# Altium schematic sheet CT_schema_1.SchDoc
size 725 x 521 mm
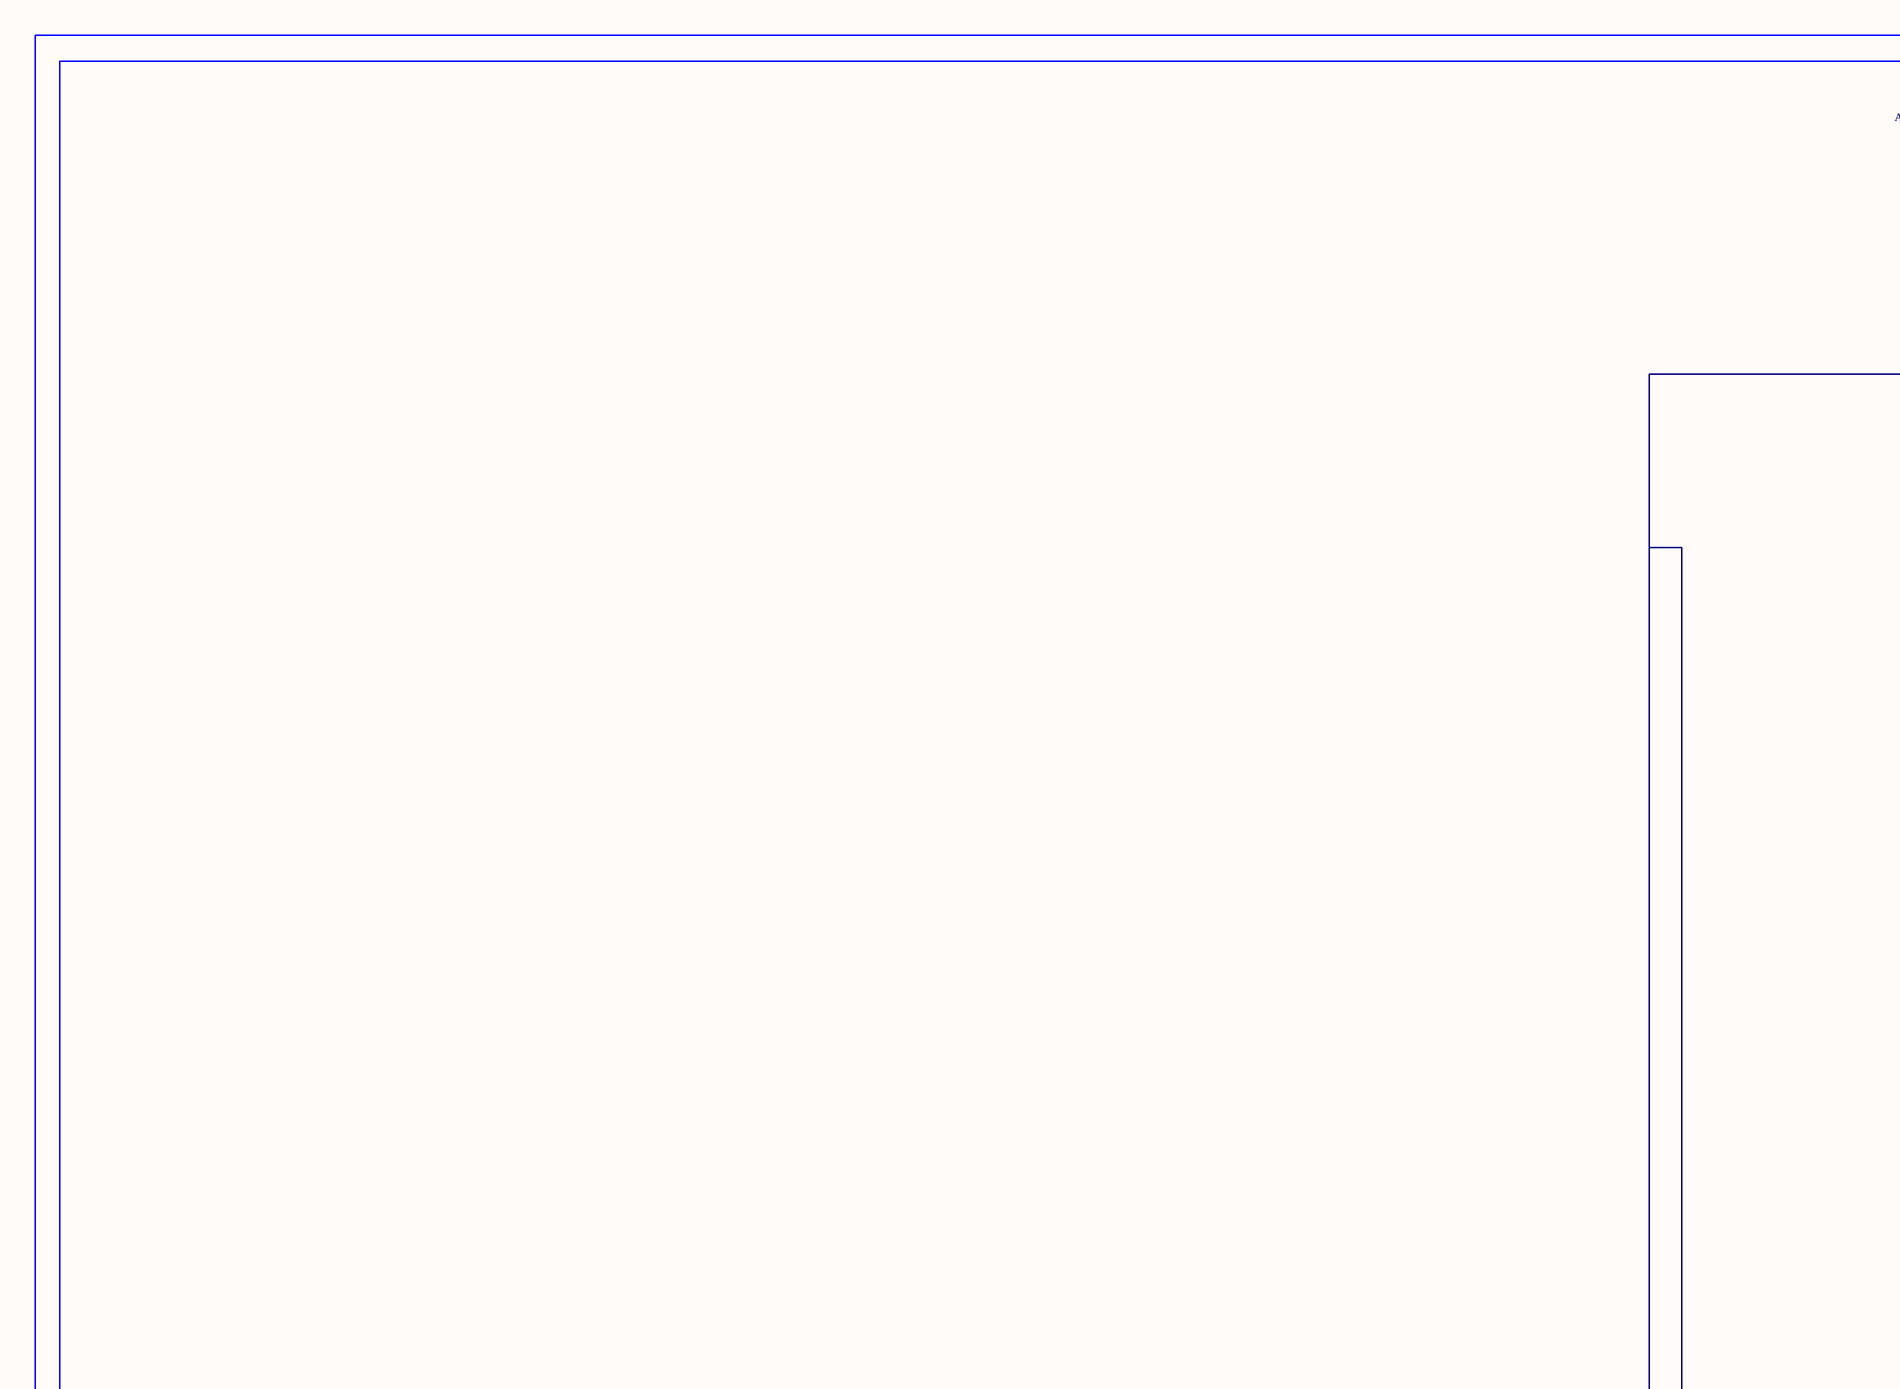
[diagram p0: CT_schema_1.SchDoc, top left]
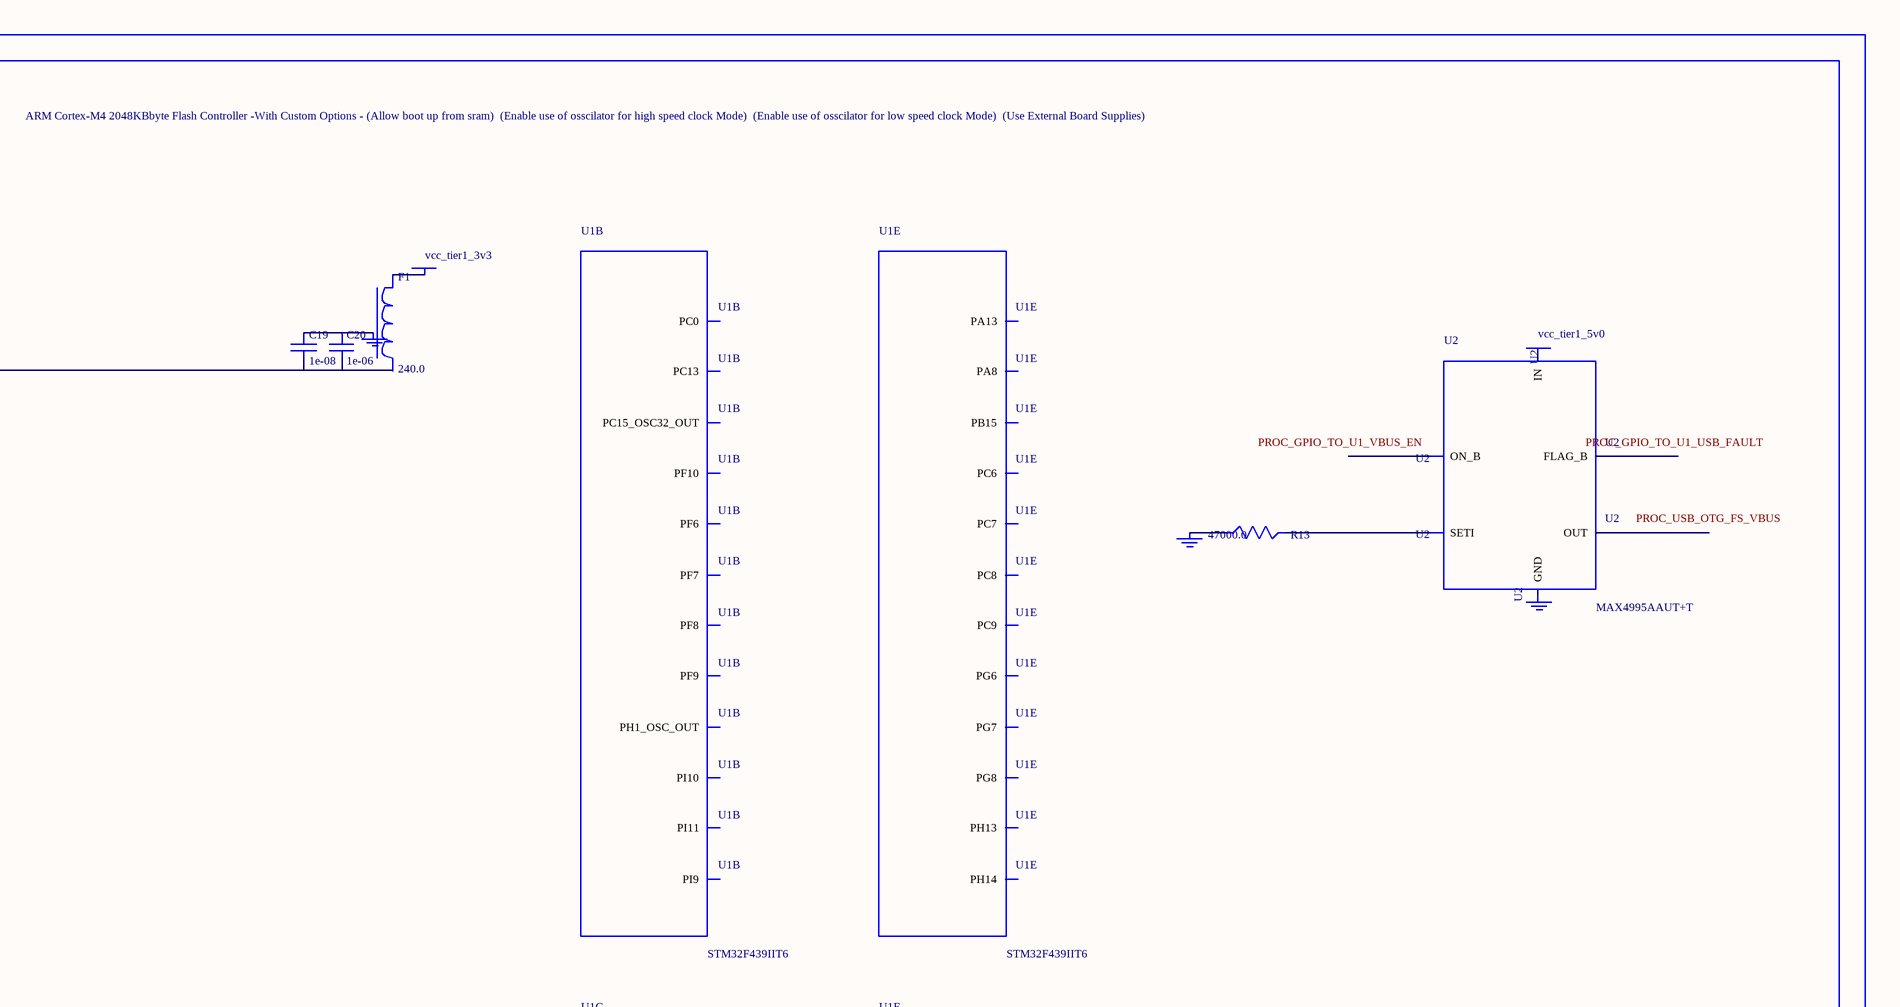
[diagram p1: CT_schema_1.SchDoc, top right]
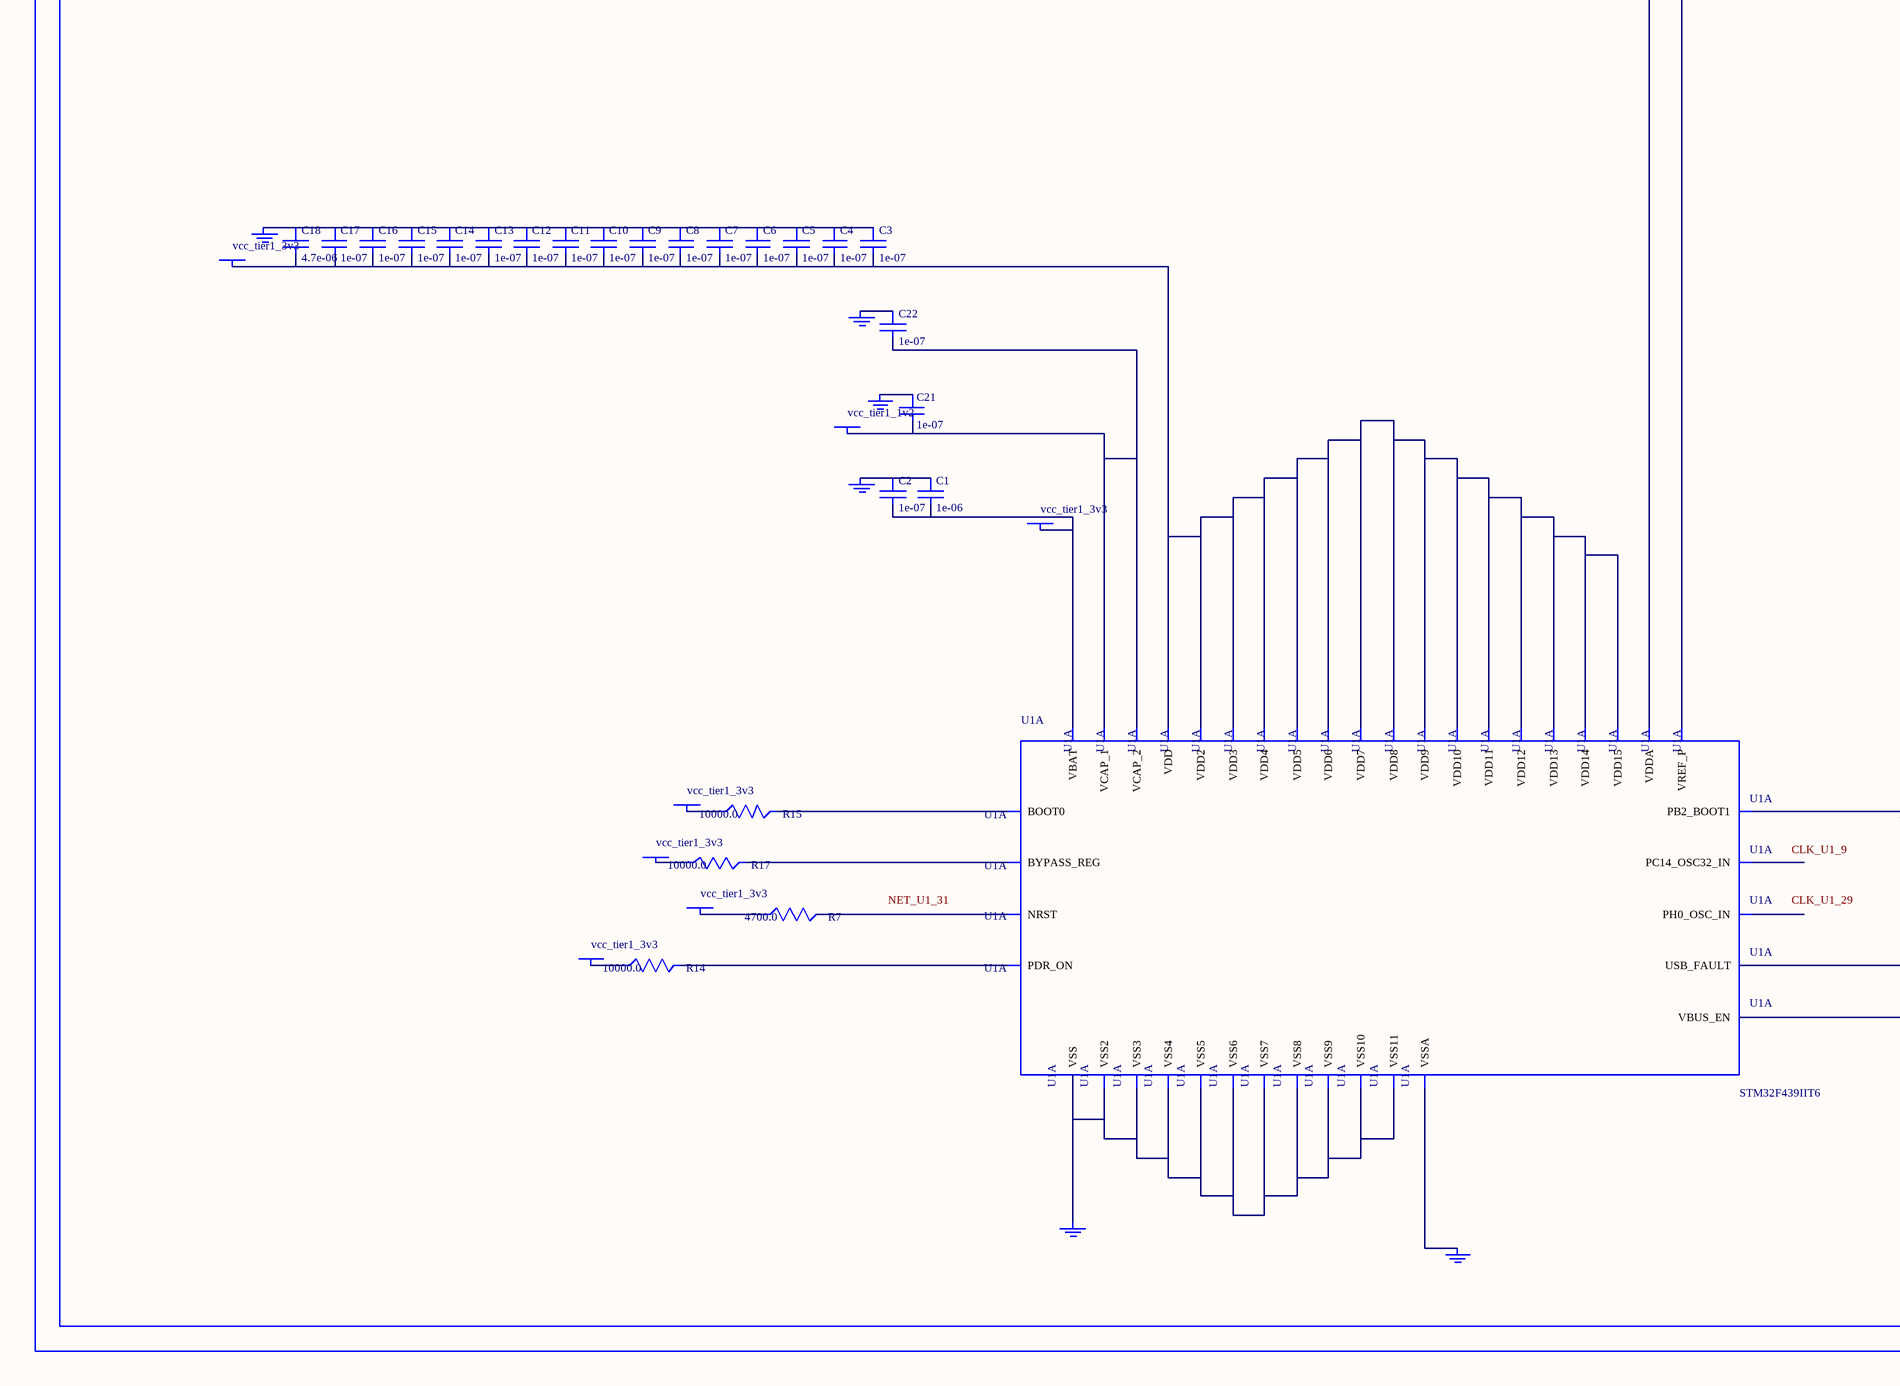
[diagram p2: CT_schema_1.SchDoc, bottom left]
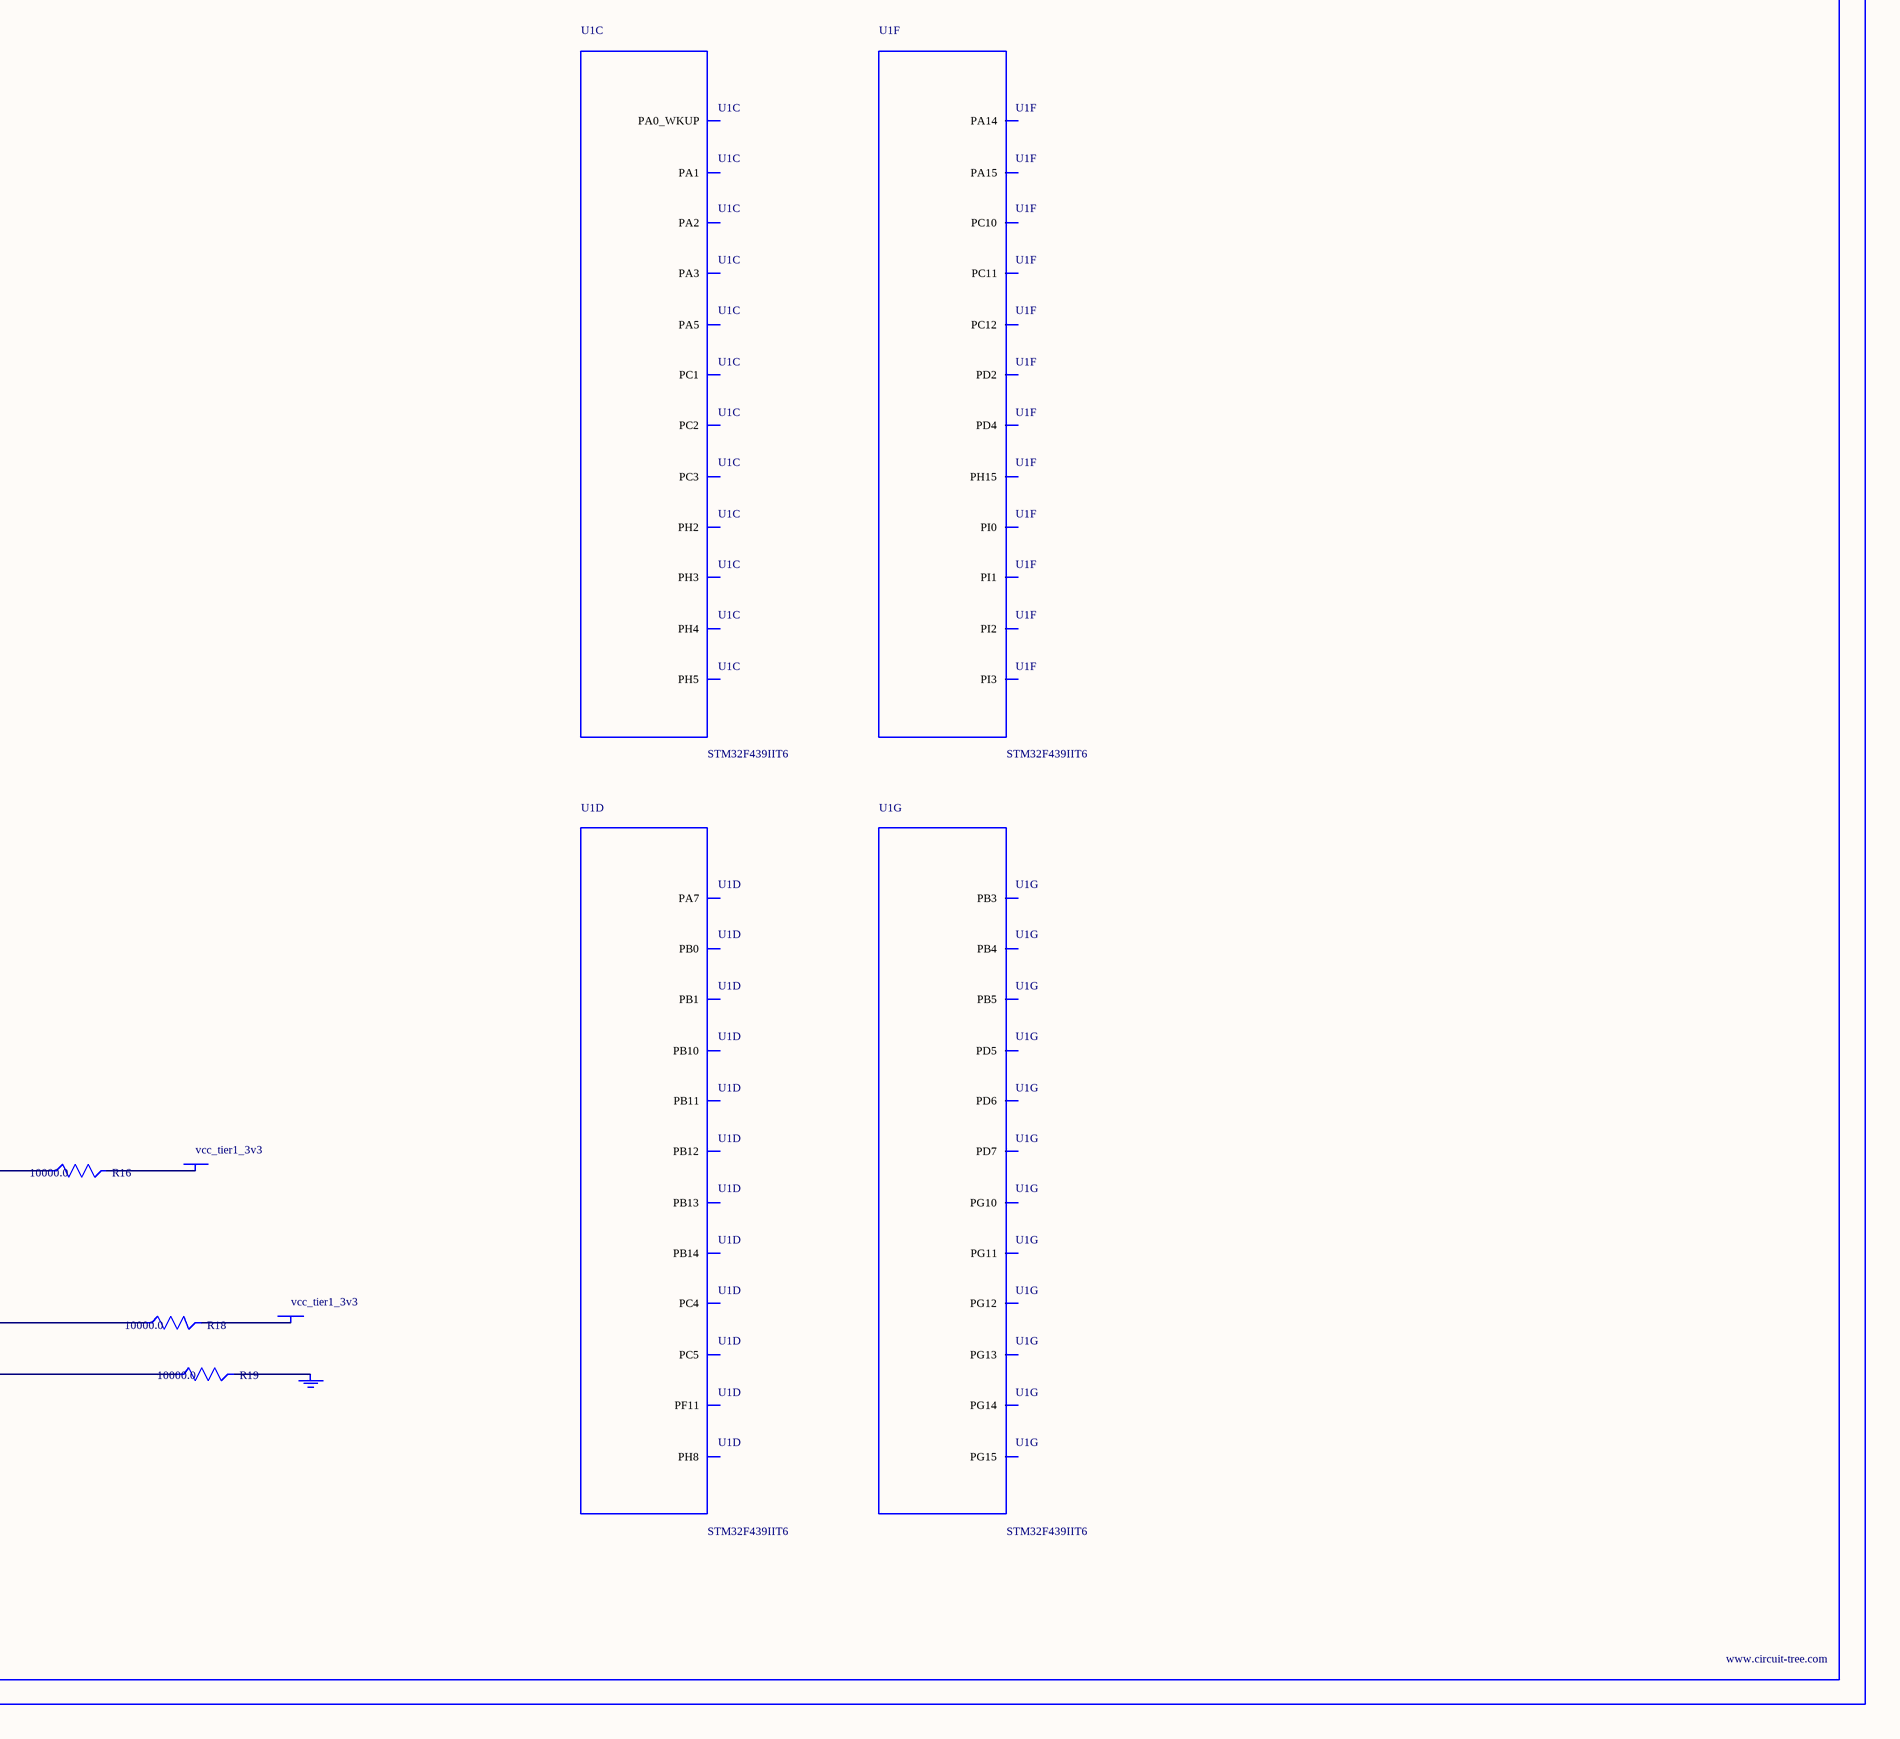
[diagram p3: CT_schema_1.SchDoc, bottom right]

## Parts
BORDER0  (no value)
C1  1e-06  [C0603]
C2  1e-07  [C0603]
C3  1e-07  [C0603]
C4  1e-07  [C0603]
C5  1e-07  [C0603]
C6  1e-07  [C0603]
C7  1e-07  [C0603]
C8  1e-07  [C0603]
C9  1e-07  [C0603]
C10  1e-07  [C0603]
C11  1e-07  [C0603]
C12  1e-07  [C0603]
C13  1e-07  [C0603]
C14  1e-07  [C0603]
C15  1e-07  [C0603]
C16  1e-07  [C0603]
C17  1e-07  [C0603]
C18  4.7e-06  [C0603]
C19  1e-08  [C0603]
C20  1e-06  [C0603]
C21  1e-07  [C0402]
C22  1e-07  [C0402]
F1  240.0  [L0603]
GND_INSTANCE_0_0  (no value)
GND_INSTANCE_0_1  (no value)
GND_INSTANCE_0_2  (no value)
GND_INSTANCE_0_3  (no value)
GND_INSTANCE_0_4  (no value)
GND_INSTANCE_0_5  (no value)
GND_INSTANCE_0_6  (no value)
GND_INSTANCE_0_7  (no value)
GND_INSTANCE_0_8  (no value)
GND_INSTANCE_0_9  (no value)
POWER_INSTANCE_0_0  vcc_tier1_3v3
POWER_INSTANCE_0_1  vcc_tier1_3v3
POWER_INSTANCE_0_2  vcc_tier1_3v3
POWER_INSTANCE_0_3  vcc_tier1_3v3
POWER_INSTANCE_0_4  vcc_tier1_3v3
POWER_INSTANCE_0_5  vcc_tier1_3v3
POWER_INSTANCE_0_6  vcc_tier1_1v2
POWER_INSTANCE_0_7  vcc_tier1_3v3
POWER_INSTANCE_0_8  vcc_tier1_3v3
POWER_INSTANCE_0_9  vcc_tier1_3v3
POWER_INSTANCE_0_10  vcc_tier1_5v0
R7  4700.0  [R0603]
R13  47000.0  [R0603]
R14  10000.0  [R0603]
R15  10000.0  [R0603]
R16  10000.0  [R0603]
R17  10000.0  [R0603]
R18  10000.0  [R0603]
R19  10000.0  [R0603]
U1  STM32F439IIT6  [LQFP176]  (parts A,B,C,D,E,F,G of 11)
U2  MAX4995AAUT+T  [SOT-23-6]

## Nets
NetC1_1: C1.1 C2.1 GND_INSTANCE_0_1.0(GND)
NetC1_2: C1.2 C2.2 POWER_INSTANCE_0_0.0(PWR) U1.6(VBAT)
NetC3_1: C3.1 C4.1 C5.1 C6.1 C7.1 C8.1 C9.1 C10.1 C11.1 C12.1 C13.1 C14.1 C15.1 C16.1 C17.1 C18.1 GND_INSTANCE_0_2.0(GND)
NetC3_2: C3.2 C4.2 C5.2 C6.2 C7.2 C8.2 C9.2 C10.2 C11.2 C12.2 C13.2 C14.2 C15.2 C16.2 C17.2 C18.2 POWER_INSTANCE_0_2.0(PWR) U1.15(VDD) U1.23(VDD2) U1.36(VDD3) U1.49(VDD4) U1.62(VDD5) U1.72(VDD6) U1.82(VDD7) U1.91(VDD8) U1.103(VDD9) U1.114(VDD10) U1.127(VDD11) U1.136(VDD12) U1.149(VDD13) U1.159(VDD14) U1.172(VDD15)
NetC19_1: C19.1 C20.1 GND_INSTANCE_0_4.0(GND)
NetC19_2: C19.2 C20.2 U1.38(VREF_P) U1.39(VDDA)
NetC21_1: C21.1 GND_INSTANCE_0_5.0(GND)
NetC21_2: C21.2 C22.2 POWER_INSTANCE_0_6.0(PWR) U1.81(VCAP_1) U1.125(VCAP_2)
NetC22_1: C22.1 GND_INSTANCE_0_6.0(GND)
NetF1_1: F1.1 POWER_INSTANCE_0_3.0(PWR)
NetGND_INSTANCE_0_0_0: GND_INSTANCE_0_0.0(GND) R19.2
NetGND_INSTANCE_0_3_0: GND_INSTANCE_0_3.0(GND) U1.37(VSSA)
NetGND_INSTANCE_0_7_0: GND_INSTANCE_0_7.0(GND) U1.14(VSS) U1.22(VSS2) U1.61(VSS3) U1.71(VSS4) U1.90(VSS5) U1.102(VSS6) U1.113(VSS7) U1.126(VSS8) U1.135(VSS9) U1.148(VSS10) U1.158(VSS11)
NetGND_INSTANCE_0_8_0: GND_INSTANCE_0_8.0(GND) R13.1
NetPOWER_INSTANCE_0_1_0: POWER_INSTANCE_0_1.0(PWR) R18.2
NetPOWER_INSTANCE_0_4_0: POWER_INSTANCE_0_4.0(PWR) R17.1
NetPOWER_INSTANCE_0_5_0: POWER_INSTANCE_0_5.0(PWR) R16.2
NetPOWER_INSTANCE_0_7_0: POWER_INSTANCE_0_7.0(PWR) R15.1
NetPOWER_INSTANCE_0_8_0: POWER_INSTANCE_0_8.0(PWR) R14.1
NetPOWER_INSTANCE_0_9_0: POWER_INSTANCE_0_9.0(PWR) R7.1
NetR7_2: R7.2 U1.31(NRST)
NetR13_2: R13.2 U2.3(SETI)
NetR14_2: R14.2 U1.171(PDR_ON)
NetR15_2: R15.2 U1.166(BOOT0)
NetR16_1: R16.1 U1.58(PB2_BOOT1)
NetR17_2: R17.2 U1.48(BYPASS_REG)
NetR18_1: R18.1 U1.7(USB_FAULT)
NetR19_1: R19.1 U1.1(VBUS_EN)

Not connected (* = marked no-connect by the designer): F1 2; GND_INSTANCE_0_9 0(GND); POWER_INSTANCE_0_10 0(PWR); U1 8(PC13) 9(PC14_OSC32_IN) 10(PC15_OSC32_OUT) 11(PI9) 12(PI10) 13(PI11) 24(PF6) 25(PF7) 26(PF8) 27(PF9) 28(PF10) 29(PH0_OSC_IN) 30(PH1_OSC_OUT) 32(PC0) 33(PC1) 34(PC2) 35(PC3) 40(PA0_WKUP) 41(PA1) 42(PA2) 43(PH2) 44(PH3) 45(PH4) 46(PH5) 47(PA3) 51(PA5) 53(PA7) 54(PC4) 55(PC5) 56(PB0) 57(PB1) 59(PF11) 79(PB10) 80(PB11) 85(PH8) 92(PB12) 93(PB13) 94(PB14) 95(PB15) 110(PG6) 111(PG7) 112(PG8) 115(PC6) 116(PC7) 117(PC8) 118(PC9) 119(PA8) 124(PA13) 128(PH13) 129(PH14) 130(PH15) 131(PI0) 132(PI1) 133(PI2) 134(PI3) 137(PA14) 138(PA15) 139(PC10) 140(PC11) 141(PC12) 144(PD2) 146(PD4) 147(PD5) 150(PD6) 151(PD7) 153(PG10) 154(PG11) 155(PG12) 156(PG13) 157(PG14) 160(PG15) 161(PB3) 162(PB4) 163(PB5); U2 1(OUT) 2(GND) 4(ON_B) 5(IN) 6(FLAG_B)

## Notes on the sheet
- Labels drawn without touching a wire or pin: CLK_U1_9, CLK_U1_29, NET_U1_31, PROC_GPIO_TO_U1_USB_FAULT, PROC_GPIO_TO_U1_VBUS_EN, PROC_USB_OTG_FS_VBUS

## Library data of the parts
BORDER0 = BORDER_PAGE0
C1 C20 = C0603C105K3RACTU
C2-C17 = 06035C104K4Z2A
C18 = GRM188R6YA475KE15D
C19 = 06035C103K4Z2A
C21 C22 = C0402C104K3RACTU
F1 = Z0603C241ASMST
GND_INSTANCE_0_0-GND_INSTANCE_0_9 = GND
POWER_INSTANCE_0_0-POWER_INSTANCE_0_10 = PWR
R7 = RC0603JR-074K7L
R13 = RC0603JR-0747KL
R14-R19 = RC0603JR-0710KL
